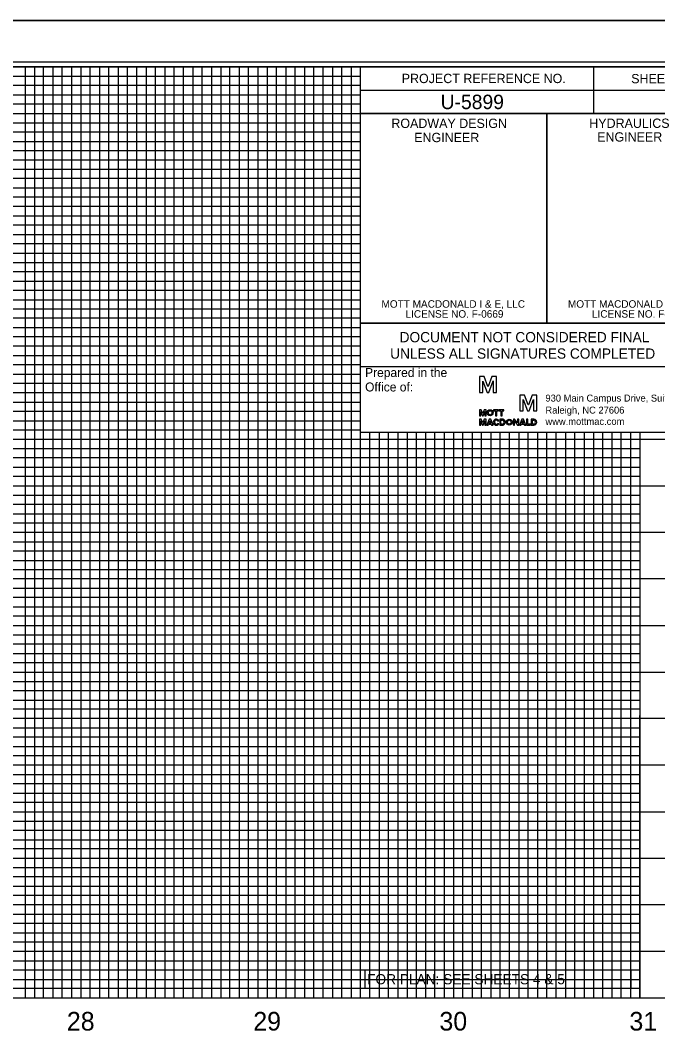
# Model space of a CAD drawing. Extents: x 1967929 to 1975641, y 546296 to 568534.
# Drawn here: x 1971149 to 1971491, y 567988 to 568534 of the extents above; entities that cross this region are included whole.
import ezdxf

# ---------------------------------------------------------------- set-up
doc = ezdxf.new("R2010")
doc.units = 0
for name, color, linetype in [('Exist Vertical Profile Horizontal Axis Label Major', 7, 'Continuous'), ('Old_Level_2', 7, 'Continuous'), ('Old_Level_42', 7, 'Continuous'), ('Old_Level_45', 7, 'Continuous'), ('Prop Grid Mask', 7, 'Continuous'), ('Scratch_Level_1', 7, 'Continuous'), ('Scratch_Level_3', 7, 'Continuous'), ('Sheet Cutting Line CELL', 7, 'Continuous'), ('Sheet Plot Border Inside CELL', 7, 'Continuous'), ('Sheet Plot Border Outside CELL', 7, 'Continuous'), ('Sheet Profile CELL', 7, 'Continuous'), ('Sheet Profile Grid Major CELL', 7, 'Continuous'), ('Sheet Profile Grid Middle CELL', 7, 'Continuous'), ('Sheet Profile Grid Minor CELL', 7, 'Continuous')]:
    doc.layers.add(name, color=color, linetype=linetype)

msp = doc.modelspace()

# ---------------------------------------------------------------- linework, layer by layer
at = {"layer": 'Old_Level_2'}
for p, q in [((1971397.84, 568342.55), (1971395.31, 568342.55)), ((1971395.31, 568342.55), (1971395.31, 568334.05)), ((1971397.11, 568334.05), (1971397.11, 568340.16)), ((1971397.11, 568340.16), (1971397.13, 568340.16)), ((1971397.13, 568340.16), (1971399.52, 568334.05)), ((1971399.89, 568337.3), (1971397.84, 568342.55)), ((1971401.99, 568342.55), (1971399.94, 568337.3)), ((1971400.3, 568334.05), (1971402.7, 568340.19)), ((1971404.52, 568342.55), (1971401.99, 568342.55)), ((1971402.7, 568340.19), (1971402.72, 568340.19)), ((1971402.72, 568340.19), (1971402.72, 568334.05)), ((1971404.52, 568334.05), (1971404.52, 568342.55)), ((1971395.31, 568334.05), (1971397.11, 568334.05)), ((1971399.52, 568334.05), (1971400.3, 568334.05)), ((1971399.89, 568337.22), (1971399.89, 568337.3)), ((1971399.94, 568337.22), (1971399.89, 568337.22)), ((1971399.94, 568337.3), (1971399.94, 568337.22)), ((1971402.72, 568334.05), (1971404.52, 568334.05)), ((1971419.45, 568332.65), (1971416.93, 568332.65)), ((1971416.93, 568332.65), (1971416.93, 568324.15)), ((1971421.5, 568327.4), (1971419.45, 568332.65)), ((1971423.61, 568332.65), (1971421.56, 568327.4)), ((1971426.13, 568332.65), (1971423.61, 568332.65)), ((1971426.13, 568324.15), (1971426.13, 568332.65)), ((1971418.72, 568324.15), (1971418.72, 568330.26)), ((1971418.72, 568330.26), (1971418.75, 568330.26)), ((1971418.75, 568330.26), (1971421.14, 568324.15)), ((1971421.5, 568327.32), (1971421.5, 568327.4)), ((1971421.56, 568327.32), (1971421.5, 568327.32)), ((1971421.56, 568327.4), (1971421.56, 568327.32)), ((1971421.92, 568324.15), (1971424.31, 568330.28)), ((1971424.31, 568330.28), (1971424.34, 568330.28)), ((1971424.34, 568330.28), (1971424.34, 568324.15)), ((1971396.28, 568324.74), (1971395.31, 568324.74)), ((1971395.31, 568324.74), (1971395.31, 568321.5)), ((1971395.31, 568321.5), (1971395.99, 568321.5)), ((1971395.99, 568321.5), (1971395.99, 568323.84)), ((1971395.99, 568323.84), (1971396.02, 568323.84)), ((1971396.02, 568323.84), (1971396.93, 568321.5)), ((1971397.08, 568322.72), (1971396.28, 568324.74)), ((1971396.93, 568321.5), (1971397.24, 568321.5)), ((1971397.89, 568324.74), (1971397.08, 568322.72)), ((1971397.24, 568321.5), (1971398.15, 568323.84)), ((1971398.85, 568324.74), (1971397.89, 568324.74)), ((1971398.15, 568323.84), (1971398.17, 568323.84)), ((1971398.15, 568323.84), (1971398.17, 568323.84)), ((1971398.17, 568323.84), (1971398.17, 568321.5)), ((1971398.17, 568321.5), (1971398.85, 568321.5)), ((1971398.85, 568321.5), (1971398.85, 568324.74)), ((1971408.54, 568324.5), (1971408.56, 568324.5)), ((1971416.93, 568324.15), (1971418.72, 568324.15)), ((1971421.14, 568324.15), (1971421.92, 568324.15)), ((1971424.34, 568324.15), (1971426.13, 568324.15)), ((1971396.28, 568319.7), (1971395.31, 568319.7)), ((1971395.31, 568319.7), (1971395.31, 568316.45)), ((1971395.31, 568316.45), (1971395.99, 568316.45)), ((1971395.99, 568316.45), (1971395.99, 568318.79)), ((1971395.99, 568318.79), (1971396.02, 568318.79)), ((1971396.02, 568318.79), (1971396.93, 568316.45)), ((1971397.08, 568317.67), (1971396.28, 568319.7)), ((1971396.93, 568316.45), (1971397.24, 568316.45)), ((1971397.89, 568319.7), (1971397.08, 568317.67)), ((1971397.24, 568316.45), (1971398.15, 568318.79)), ((1971398.85, 568319.7), (1971397.89, 568319.7)), ((1971398.15, 568318.79), (1971398.17, 568318.79)), ((1971398.17, 568318.79), (1971398.17, 568316.45)), ((1971398.17, 568316.45), (1971398.85, 568316.45)), ((1971398.85, 568316.45), (1971398.85, 568319.7)), ((1971405.67, 568317.12), (1971405.11, 568317.4)), ((1971405.19, 568318.64), (1971405.76, 568318.9)), ((1971407.69, 568319.7), (1971406.2, 568319.7)), ((1971406.2, 568319.7), (1971406.2, 568318.02)), ((1971406.2, 568318.02), (1971406.2, 568316.45)), ((1971406.2, 568316.45), (1971407.69, 568316.45)), ((1971406.88, 568317.08), (1971406.88, 568319.1)), ((1971406.88, 568319.1), (1971407.69, 568319.1)), ((1971407.69, 568317.08), (1971406.88, 568317.08)), ((1971423.02, 568319.7), (1971423.02, 568319.7)), ((1971424.51, 568319.7), (1971423.02, 568319.7)), ((1971423.02, 568319.7), (1971423.02, 568318.02)), ((1971423.02, 568318.02), (1971423.02, 568316.45)), ((1971423.02, 568316.45), (1971424.51, 568316.45)), ((1971423.7, 568317.08), (1971423.7, 568319.1)), ((1971423.7, 568319.1), (1971424.51, 568319.1)), ((1971424.51, 568317.08), (1971423.7, 568317.08)), ((1971424.51, 568319.08), (1971424.51, 568319.08))]:
    msp.add_line(p, q, dxfattribs=at)
for points in [[(1971402.93, 568324.15), (1971403.87, 568324.15), (1971403.87, 568321.5), (1971404.57, 568321.5), (1971404.57, 568324.15), (1971405.5, 568324.15), (1971405.5, 568324.74), (1971402.93, 568324.74), (1971402.93, 568324.15)], [(1971405.92, 568324.15), (1971406.85, 568324.15), (1971406.85, 568321.5), (1971407.56, 568321.5), (1971407.56, 568324.15), (1971408.49, 568324.15), (1971408.49, 568324.74), (1971405.92, 568324.74), (1971405.92, 568324.15)], [(1971399.24, 568316.45), (1971400.02, 568316.45), (1971400.23, 568317), (1971401.63, 568317), (1971401.84, 568316.45), (1971402.59, 568316.45), (1971401.34, 568319.7), (1971400.49, 568319.7), (1971399.24, 568316.45)], [(1971400.41, 568317.6), (1971400.93, 568319), (1971401.45, 568317.6), (1971400.41, 568317.6)], [(1971414.16, 568318.56), (1971414.19, 568318.56), (1971415.75, 568316.45), (1971416.4, 568316.45), (1971416.39, 568319.7), (1971415.72, 568319.7), (1971415.72, 568317.65), (1971414.18, 568319.7), (1971413.51, 568319.7), (1971413.51, 568316.45), (1971414.16, 568316.45), (1971414.16, 568318.56)], [(1971416.81, 568316.45), (1971417.59, 568316.45), (1971417.8, 568317), (1971419.2, 568317), (1971419.41, 568316.45), (1971420.16, 568316.45), (1971418.92, 568319.7), (1971418.06, 568319.7), (1971416.81, 568316.45)], [(1971417.98, 568317.6), (1971418.5, 568319), (1971419.02, 568317.6), (1971417.98, 568317.6)], [(1971422.63, 568316.45), (1971422.63, 568317.03), (1971421.23, 568317.02), (1971421.23, 568319.7), (1971420.55, 568319.7), (1971420.55, 568316.45), (1971422.63, 568316.45)]]:
    msp.add_lwpolyline(points, dxfattribs=at)
msp.add_arc((1971424.51, 568318.08), 1.62, 270, 90, dxfattribs=at)
for centre, major_axis, ratio in [((1971401.06, 568323.12), (0, 1.62), 0.993118), ((1971401.06, 568323.12), (0, 1.06), 0.916103), ((1971411.33, 568318.08), (0, 1.62), 0.993118), ((1971411.33, 568318.08), (0, 1.06), 0.916103)]:
    msp.add_ellipse(centre, major_axis=major_axis, ratio=ratio, dxfattribs=at)
for centre, major_axis, ratio, start_param, end_param in [((1971404.37, 568318.08), (0, 1.62), 0.993118, 5.246647, 10.366427), ((1971404.37, 568318.08), (0, 1.06), 0.916103, 5.276876, 10.296021), ((1971407.69, 568318.08), (0, -1.62), 0.930276, 0, 3.141593), ((1971407.69, 568318.09), (0, -1.01), 0.900832, 0, 3.141593), ((1971424.51, 568318.09), (0, -1.01), 0.900832, 0, 3.141593)]:
    msp.add_ellipse(centre, major_axis=major_axis, ratio=ratio, start_param=start_param, end_param=end_param, dxfattribs=at)
at = {"layer": 'Old_Level_42'}
msp.add_lwpolyline([(1971531.45, 568312.51), (1971331.4, 568312.51), (1971331.4, 568347.81)], dxfattribs=at)
at = {"layer": 'Prop Grid Mask'}
msp.add_lwpolyline([(1971334.04, 568023.93), (1971476.5, 568023.93), (1971476.5, 568013.91), (1971334.04, 568013.91)], close=True, dxfattribs=at)
at = {"layer": 'Scratch_Level_1'}
for p, q in [((1971331.4, 568347.81), (1971331.4, 568371.31)), ((1971331.4, 568371.31), (1971531.44, 568371.31)), ((1971531.44, 568347.81), (1971331.4, 568347.81))]:
    msp.add_line(p, q, dxfattribs=at)
at = {"layer": 'Scratch_Level_3'}
for points in [[(1970081.45, 568508.86), (1970081.45, 568008.86), (1971481.45, 568008.86), (1971481.5, 568312.51), (1971331.45, 568312.51), (1971331.4, 568508.86)], [(1970081.45, 568508.86), (1970081.45, 568008.86), (1971331.45, 568008.86), (1971331.45, 568277.21), (1971331.45, 568277.21), (1971331.45, 568508.86)], [(1970081.45, 568508.86), (1970081.45, 568008.86), (1971481.45, 568008.86), (1971481.5, 568312.53), (1971331.45, 568312.51), (1971331.4, 568508.86)]]:
    msp.add_lwpolyline(points, close=True, dxfattribs=at)
at = {"layer": 'Sheet Cutting Line CELL'}
msp.add_line((1969864.45, 568533.86), (1971548.45, 568533.86), dxfattribs=at)
at = {"layer": 'Sheet Plot Border Inside CELL'}
msp.add_lwpolyline([(1969877.45, 567456.31), (1971543.95, 567456.31), (1971543.95, 568511.41), (1969877.45, 568511.41)], close=True, dxfattribs=at)
at = {"layer": 'Sheet Plot Border Outside CELL'}
msp.add_lwpolyline([(1969864.45, 567433.86), (1971548.45, 567433.86), (1971548.45, 568533.86), (1969864.45, 568533.86)], close=True, dxfattribs=at)
at = {"layer": 'Sheet Profile CELL'}
for p, q in [((1971456.45, 568508.81), (1971456.45, 568483.81)), ((1971331.4, 568496.31), (1971531.45, 568496.31)), ((1971431.45, 568483.81), (1971431.45, 568371.36)), ((1970031.45, 568008.86), (1971531.45, 568008.86))]:
    msp.add_line(p, q, dxfattribs=at)
for points in [[(1971531.45, 568508.86), (1970031.45, 568508.86), (1970031.45, 567458.86), (1971531.45, 567458.86)], [(1971331.4, 568508.86), (1971531.45, 568508.86), (1971531.45, 568483.81), (1971331.4, 568483.81)], [(1971331.4, 568483.81), (1971431.45, 568483.81), (1971431.45, 568371.31), (1971331.4, 568371.31)], [(1971431.45, 568483.81), (1971531.45, 568483.81), (1971531.45, 568371.31), (1971431.45, 568371.31)]]:
    msp.add_lwpolyline(points, close=True, dxfattribs=at)
msp.add_lwpolyline([(1971531.45, 568312.51), (1971331.4, 568312.51), (1971331.4, 568347.81)], dxfattribs=at)
at = {"layer": 'Sheet Profile Grid Major CELL'}
for points in [[(1971331.45, 568458.86), (1970031.45, 568458.86), (1970031.45, 568508.86), (1971331.45, 568508.86)], [(1971181.45, 568508.86), (1971181.45, 568008.86), (1971231.45, 568008.86), (1971231.45, 568508.86)], [(1971281.45, 568508.86), (1971281.45, 568008.86), (1971331.45, 568008.86), (1971331.45, 568508.86)], [(1971331.45, 568358.86), (1970031.45, 568358.86), (1970031.45, 568408.86), (1971331.45, 568408.86)], [(1971381.45, 568312.51), (1971381.45, 568008.86), (1971431.45, 568008.86), (1971431.45, 568312.51)], [(1971481.45, 568312.51), (1971481.45, 568008.86), (1971531.45, 568008.86)], [(1971531.45, 568258.86), (1970031.45, 568258.86), (1970031.45, 568308.86), (1971331.4, 568308.86)], [(1971531.45, 568258.86), (1970031.45, 568258.86), (1970031.45, 568308.86), (1971531.45, 568308.86)], [(1971381.45, 568277.21), (1971381.45, 568008.86), (1971431.45, 568008.86), (1971431.45, 568277.21)], [(1971481.45, 568277.21), (1971481.45, 568008.86), (1971531.45, 568008.86)], [(1971531.45, 568158.86), (1970031.45, 568158.86), (1970031.45, 568208.86), (1971531.45, 568208.86)], [(1971531.45, 568058.86), (1970031.45, 568058.86), (1970031.45, 568108.86), (1971531.45, 568108.86)]]:
    msp.add_lwpolyline(points, dxfattribs=at)
at = {"layer": 'Sheet Profile Grid Middle CELL'}
for points in [[(1970031.45, 568508.86), (1970031.45, 568483.86), (1971331.45, 568483.86)], [(1971156.45, 568508.86), (1971156.45, 568008.86), (1971206.45, 568008.86), (1971206.45, 568508.86)], [(1971256.45, 568508.86), (1971256.45, 568008.86), (1971306.45, 568008.86), (1971306.45, 568508.86)], [(1971331.45, 568433.86), (1970031.45, 568433.86), (1970031.45, 568383.86), (1971331.45, 568383.86)], [(1971331.45, 568333.86), (1970031.45, 568333.86), (1970031.45, 568283.86), (1971331.4, 568283.86)], [(1971331.45, 568333.86), (1970031.45, 568333.86), (1970031.45, 568283.86), (1971531.45, 568283.86)], [(1971356.45, 568312.51), (1971356.45, 568008.86), (1971406.45, 568008.86), (1971406.45, 568312.51)], [(1971456.45, 568312.51), (1971456.45, 568008.86)], [(1971356.45, 568277.21), (1971356.45, 568008.86), (1971406.45, 568008.86), (1971406.45, 568277.21)], [(1971456.45, 568277.21), (1971456.45, 568008.86)], [(1971531.45, 568233.86), (1970031.45, 568233.86), (1970031.45, 568183.86), (1971531.45, 568183.86)], [(1971531.45, 568133.86), (1970031.45, 568133.86), (1970031.45, 568083.86), (1971531.45, 568083.86)], [(1971531.45, 568033.86), (1970031.45, 568033.86)]]:
    msp.add_lwpolyline(points, dxfattribs=at)
at = {"layer": 'Sheet Profile Grid Minor CELL'}
for points in [[(1971151.45, 568508.86), (1971151.45, 568008.86), (1971161.45, 568008.86), (1971161.45, 568508.86)], [(1971166.45, 568508.86), (1971166.45, 568008.86), (1971171.45, 568008.86), (1971171.45, 568508.86)], [(1971176.45, 568508.86), (1971176.45, 568008.86), (1971186.45, 568008.86), (1971186.45, 568508.86)], [(1971191.45, 568508.86), (1971191.45, 568008.86), (1971196.45, 568008.86), (1971196.45, 568508.86)], [(1971201.45, 568508.86), (1971201.45, 568008.86), (1971211.45, 568008.86), (1971211.45, 568508.86)], [(1971216.45, 568508.86), (1971216.45, 568008.86), (1971221.45, 568008.86), (1971221.45, 568508.86)], [(1971226.45, 568508.86), (1971226.45, 568008.86), (1971236.45, 568008.86), (1971236.45, 568508.86)], [(1971241.45, 568508.86), (1971241.45, 568008.86), (1971246.45, 568008.86), (1971246.45, 568508.86)], [(1971251.45, 568508.86), (1971251.45, 568008.86), (1971261.45, 568008.86), (1971261.45, 568508.86)], [(1971266.45, 568508.86), (1971266.45, 568008.86), (1971271.45, 568008.86), (1971271.45, 568508.86)], [(1971276.45, 568508.86), (1971276.45, 568008.86), (1971286.45, 568008.86), (1971286.45, 568508.86)], [(1971291.45, 568508.86), (1971291.45, 568008.86), (1971296.45, 568008.86), (1971296.45, 568508.86)], [(1971301.45, 568508.86), (1971301.45, 568008.86), (1971311.45, 568008.86), (1971311.45, 568508.86)], [(1971316.45, 568508.86), (1971316.45, 568008.86), (1971321.45, 568008.86), (1971321.45, 568508.86)], [(1971326.45, 568508.86), (1971326.45, 568008.86), (1971336.45, 568008.86), (1971336.45, 568277.21)], [(1971326.45, 568508.86), (1971326.45, 568008.86), (1971336.45, 568008.86), (1971336.45, 568312.51)], [(1970081.45, 568503.86), (1971331.45, 568503.86)], [(1971331.45, 568498.86), (1970081.45, 568498.86), (1970081.45, 568493.86), (1971331.45, 568493.86)], [(1971331.45, 568488.86), (1970081.45, 568488.86), (1970081.45, 568478.86), (1971331.45, 568478.86)], [(1971331.45, 568473.86), (1970081.45, 568473.86), (1970081.45, 568468.86), (1971331.45, 568468.86)], [(1971331.45, 568463.86), (1970081.45, 568463.86), (1970081.45, 568453.86), (1971331.45, 568453.86)], [(1971331.45, 568448.86), (1970081.45, 568448.86), (1970081.45, 568443.86), (1971331.45, 568443.86)], [(1971331.45, 568438.86), (1970081.45, 568438.86), (1970081.45, 568428.86), (1971331.45, 568428.86)], [(1971331.45, 568423.86), (1970081.45, 568423.86), (1970081.45, 568418.86), (1971331.45, 568418.86)], [(1971331.45, 568413.86), (1970081.45, 568413.86), (1970081.45, 568403.86), (1971331.45, 568403.86)], [(1971331.45, 568398.86), (1970081.45, 568398.86), (1970081.45, 568393.86), (1971331.45, 568393.86)], [(1971331.45, 568388.86), (1970081.45, 568388.86), (1970081.45, 568378.86), (1971331.45, 568378.86)], [(1971331.45, 568373.86), (1970081.45, 568373.86), (1970081.45, 568368.86), (1971331.45, 568368.86)], [(1971331.45, 568363.86), (1970081.45, 568363.86), (1970081.45, 568353.86), (1971331.45, 568353.86)], [(1971331.45, 568348.86), (1970081.45, 568348.86), (1970081.45, 568343.86), (1971331.45, 568343.86)], [(1971331.45, 568338.86), (1970081.45, 568338.86), (1970081.45, 568328.86), (1971331.45, 568328.86)], [(1971331.45, 568323.86), (1970081.45, 568323.86), (1970081.45, 568318.86), (1971331.45, 568318.86)], [(1971331.45, 568313.86), (1970081.45, 568313.86), (1970081.45, 568303.86), (1971331.4, 568303.86)], [(1971331.45, 568313.86), (1970081.45, 568313.86), (1970081.45, 568303.86), (1971481.45, 568303.86)], [(1971341.45, 568312.51), (1971341.45, 568008.86), (1971346.45, 568008.86), (1971346.45, 568312.51)], [(1971351.45, 568312.51), (1971351.45, 568008.86), (1971361.45, 568008.86), (1971361.45, 568312.51)], [(1971366.45, 568312.51), (1971366.45, 568008.86), (1971371.45, 568008.86), (1971371.45, 568312.51)], [(1971376.45, 568312.51), (1971376.45, 568008.86), (1971386.45, 568008.86), (1971386.45, 568312.52)], [(1971391.45, 568312.51), (1971391.45, 568008.86), (1971396.45, 568008.86), (1971396.45, 568312.51)], [(1971401.45, 568312.51), (1971401.45, 568008.86), (1971411.45, 568008.86), (1971411.45, 568312.51)], [(1971416.45, 568312.51), (1971416.45, 568008.86)], [(1971416.45, 568008.86), (1971421.45, 568008.86), (1971421.45, 568312.51)], [(1971426.45, 568312.51), (1971426.45, 568008.86), (1971436.45, 568008.86), (1971436.45, 568312.51)], [(1971441.45, 568312.51), (1971441.45, 568008.86), (1971446.45, 568008.86), (1971446.45, 568312.51)], [(1971451.45, 568312.51), (1971451.45, 568008.86), (1971461.45, 568008.86), (1971461.45, 568312.51)], [(1971466.45, 568312.51), (1971466.45, 568008.86), (1971471.45, 568008.86), (1971471.45, 568312.51)], [(1971476.45, 568312.51), (1971476.45, 568008.86), (1971486.45, 568008.86)], [(1971331.4, 568298.86), (1970081.45, 568298.86), (1970081.45, 568293.86), (1971331.4, 568293.86)], [(1971481.45, 568298.86), (1970081.45, 568298.86), (1970081.45, 568293.86), (1971481.45, 568293.86)], [(1971331.4, 568288.86), (1970081.45, 568288.86), (1970081.45, 568278.86), (1971331.4, 568278.86)], [(1971481.45, 568288.86), (1970081.45, 568288.86), (1970081.45, 568278.86), (1971481.45, 568278.86)], [(1971481.45, 568273.86), (1970081.45, 568273.86), (1970081.45, 568268.86), (1971481.45, 568268.86)], [(1971341.45, 568277.21), (1971341.45, 568008.86), (1971346.45, 568008.86), (1971346.45, 568277.21)], [(1971351.45, 568277.21), (1971351.45, 568008.86), (1971361.45, 568008.86), (1971361.45, 568277.21)], [(1971366.45, 568277.21), (1971366.45, 568008.86), (1971371.45, 568008.86), (1971371.45, 568277.21)], [(1971376.45, 568277.21), (1971376.45, 568008.86), (1971386.45, 568008.86), (1971386.45, 568277.21)], [(1971391.45, 568277.21), (1971391.45, 568008.86), (1971396.45, 568008.86), (1971396.45, 568277.21)], [(1971401.45, 568277.21), (1971401.45, 568008.86), (1971411.45, 568008.86), (1971411.45, 568277.21)], [(1971416.45, 568277.21), (1971416.45, 568008.86)], [(1971416.45, 568008.86), (1971421.45, 568008.86), (1971421.45, 568277.21)], [(1971426.45, 568277.21), (1971426.45, 568008.86), (1971436.45, 568008.86), (1971436.45, 568277.21)], [(1971441.45, 568277.21), (1971441.45, 568008.86), (1971446.45, 568008.86), (1971446.45, 568277.21)], [(1971451.45, 568277.21), (1971451.45, 568008.86), (1971461.45, 568008.86), (1971461.45, 568277.21)], [(1971466.45, 568277.21), (1971466.45, 568008.86), (1971471.45, 568008.86), (1971471.45, 568277.21)], [(1971476.45, 568277.21), (1971476.45, 568008.86), (1971486.45, 568008.86)], [(1971481.45, 568263.86), (1970081.45, 568263.86), (1970081.45, 568253.86), (1971481.45, 568253.86)], [(1971481.45, 568248.86), (1970081.45, 568248.86), (1970081.45, 568243.86), (1971481.45, 568243.86)], [(1971481.45, 568238.86), (1970081.45, 568238.86), (1970081.45, 568228.86), (1971481.45, 568228.86)], [(1971481.45, 568223.86), (1970081.45, 568223.86), (1970081.45, 568218.86), (1971481.45, 568218.86)], [(1971481.45, 568213.86), (1970081.45, 568213.86)], [(1970081.45, 568203.86), (1971481.45, 568203.86)], [(1971481.45, 568198.86), (1970081.45, 568198.86), (1970081.45, 568193.86), (1971481.45, 568193.86)], [(1971481.45, 568188.86), (1970081.45, 568188.86)], [(1970081.45, 568178.86), (1971481.45, 568178.86)], [(1971481.45, 568173.86), (1970081.45, 568173.86), (1970081.45, 568168.86), (1971481.45, 568168.86)], [(1971481.45, 568163.86), (1970081.45, 568163.86), (1970081.45, 568153.86), (1971481.45, 568153.86)], [(1971481.45, 568148.86), (1970081.45, 568148.86), (1970081.45, 568143.86), (1971481.45, 568143.86)], [(1971481.45, 568138.86), (1970081.45, 568138.86), (1970081.45, 568128.86), (1971481.45, 568128.86)], [(1971481.45, 568123.86), (1970081.45, 568123.86), (1970081.45, 568118.86), (1971481.45, 568118.86)], [(1971481.45, 568113.86), (1970081.45, 568113.86), (1970081.45, 568103.86), (1971481.45, 568103.86)], [(1971481.45, 568098.86), (1970081.45, 568098.86), (1970081.45, 568093.86), (1971481.45, 568093.86)], [(1971481.45, 568088.86), (1970081.45, 568088.86), (1970081.45, 568078.86), (1971481.45, 568078.86)], [(1971481.45, 568073.86), (1970081.45, 568073.86), (1970081.45, 568068.86), (1971481.45, 568068.86)], [(1971481.45, 568063.86), (1970081.45, 568063.86), (1970081.45, 568053.86), (1971481.45, 568053.86)], [(1971481.45, 568048.86), (1970081.45, 568048.86), (1970081.45, 568043.86), (1971481.45, 568043.86)], [(1971481.45, 568038.86), (1970081.45, 568038.86), (1970081.45, 568028.86), (1971481.45, 568028.86)], [(1971481.45, 568023.86), (1970081.45, 568023.86), (1970081.45, 568018.86), (1971481.45, 568018.86)], [(1971481.45, 568013.86), (1970081.45, 568013.86), (1970081.45, 568008.86), (1971481.45, 568008.86)]]:
    msp.add_lwpolyline(points, dxfattribs=at)

# ---------------------------------------------------------------- texts
at = {"layer": 'Exist Vertical Profile Horizontal Axis Label Major'}
for s, p in [('28', (1971173.92, 567991.36)), ('29', (1971273.96, 567991.36)), ('30', (1971373.84, 567991.36)), ('31', (1971475.81, 567991.36))]:
    msp.add_text(s, height=10, dxfattribs=at).set_placement(p)
at = {"layer": 'Old_Level_2'}
for s, height, p in [('Prepared in the ', 4.8186, (1971333.95, 568342.31)), ('Office of:', 4.819, (1971333.95, 568334.56))]:
    msp.add_text(s, height=height, dxfattribs=at).set_placement(p)
for s, p in [('930 Main Campus Drive, Suite 200', (1971430.73, 568329.13)), ('Raleigh, NC 27606', (1971430.73, 568322.68)), ('www.mottmac.com', (1971430.73, 568316.59))]:
    msp.add_text(s, height=3.75, rotation=360, dxfattribs=at).set_placement(p)
at = {"layer": 'Old_Level_45'}
for s, p in [('MOTT MACDONALD I & E, LLC', (1971342.76, 568379.54)), ('MOTT MACDONALD I & E, LLC', (1971442.81, 568379.54)), (' LICENSE NO. F-0669', (1971354.15, 568374.19)), (' LICENSE NO. F-0669', (1971454.2, 568374.19))]:
    msp.add_text(s, height=4.0179, dxfattribs=at).set_placement(p)
at = {"layer": 'Prop Grid Mask'}
msp.add_text('FOR PLAN: SEE SHEETS 4 & 5', height=5.4932, dxfattribs=at).set_placement((1971335.03, 568016.19))
at = {"layer": 'Scratch_Level_1'}
for s, p in [('DOCUMENT NOT CONSIDERED FINAL', (1971352.47, 568360.97)), ('UNLESS ALL SIGNATURES COMPLETED', (1971347.4, 568352.17))]:
    msp.add_text(s, height=5.5, dxfattribs=at).set_placement(p)
at = {"layer": 'Sheet Profile CELL'}
for s, height, p in [('PROJECT REFERENCE NO.', 5.0001, (1971353.6, 568500.16)), ('SHEET NO.', 5, (1971476.75, 568500.06)), ('U-5899', 7.75, (1971374.47, 568486.19)), ('ROADWAY DESIGN', 5.0001, (1971348.05, 568476.06)), ('HYDRAULICS', 5, (1971454.25, 568476.11)), ('ENGINEER', 5, (1971360.3, 568468.46)), ('ENGINEER', 5, (1971458.5, 568468.76))]:
    msp.add_text(s, height=height, dxfattribs=at).set_placement(p)

doc.saveas('drawing.dxf')
